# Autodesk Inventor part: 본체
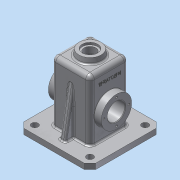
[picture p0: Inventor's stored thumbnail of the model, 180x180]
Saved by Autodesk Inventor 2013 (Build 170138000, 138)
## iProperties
Created: 2016-02
Part Number: 본체
Material: 알루미늄 6061
Document SubType Name: Modeling
Designer: dgall
Mass: 938.846 g
Surface Area: 1045.65 cm^2
Volume: 346.438 cm^3
Density: 2.71 g/cm^3
Author: dgall
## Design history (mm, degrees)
sketch "스케치1"
  geometry: L1 (-35, 35)-(35, 35); L2 (35, 35)-(35, -35); L3 (35, -35)-(-35, -35); L4 (-35, -35)-(-35, 35); 1 further point
  constraints: 8 end point, 2 parallel, 1 horizontal, 1 perpendicular
  dimensions: "d0" = 70 distance of L1.end L2.end; "d2" = 70 distance of L1.start L1.end; "d3" = 35 distance from line of point (0, 0) L1; "d4" = 35 distance from line of point (0, 0) L2
extrude "돌출1" new body sketch "스케치1" distance "d5" = 120; taper "d6" = 0 deg
feature "쉘1" dims "d7" = 5
fillet "모깎기1" dims "d8" = 8
fillet "모깎기2" dims "d9" = 8
fillet "모깎기3" dims "d10" = 3
fillet "모깎기4" dims "d11" = 3
sketch "스케치2"
  geometry: L1 (-35, 27)-(-35, -27) reference; L2 (-27, -35)-(27, -35) reference; L3 (35, -27)-(35, 27) reference; L4 (27, 35)-(-27, 35) reference; L5 (-65, 65)-(65, 65); L6 (65, 65)-(65, -65); L7 (65, -65)-(-65, -65); L8 (-65, -65)-(-65, 65); A1 r 8 centre (-27, 27) between (-27, 35) and (-35, 27) reference; A2 r 8 centre (-27, -27) between (-35, -27) and (-27, -35) reference; A3 r 8 centre (27, -27) between (27, -35) and (35, -27) reference; A4 r 8 centre (27, 27) between (35, 27) and (27, 35) reference; 1 further point
  constraints: 8 end point, 2 parallel, 1 horizontal, 1 perpendicular
  dimensions: "d12" = 130 distance of L5.start L5.end; "d14" = 130 distance of L5.end L6.end; "d15" = 65 distance from line of point (0, 0) L6; "d16" = 65 distance from line of point (0, 0) L5
extrude "돌출2" join sketch "스케치2" distance "d17" = 10; taper "d18" = 0 deg
sketch "스케치3"
  geometry: L1 (-35, 10)-(-35, 112) reference; L2 (65, 10)-(-65, 10) reference; L3 (-50, 10)-(-35, 95.069); L4 (-65, 0)-(-65, 10) reference; 1 further point
  constraints: 2 end point, 2 point on line
  dimensions: "d19" = 15 distance from line of L3.start L4; "d20" = 10 deg angle of L4 L3
feature "리브1" sketch "스케치3" dims "d21" = 1, "d22" = 10, "d23" = 0, "d24" = 0, "d25" = 1, "d26" = 1
sketch "스케치4"
  geometry: L1 (35, 10)-(27, 10) reference; L2 (27, 10)-(27, 112) reference; L3 (35, 112)-(27, 112) reference; L4 (35, 112)-(35, 10) reference; L5 (65, 10)-(-65, 10) reference; L6 (35, 95.069)-(50, 10); L7 (65, 0)-(65, 10) reference; 1 further point
  constraints: 2 end point, 2 point on line
  dimensions: "d27" = 15 distance from line of L7 L6.end; "d28" = 10 deg angle of L7 L6
feature "리브2" sketch "스케치4" dims "d29" = 1, "d30" = 10, "d31" = 0, "d32" = 0, "d33" = 1, "d34" = 1
node "작업 평면1"
sketch "스케치5"
  geometry: C1 r 27.5 at (0, 55); 1 further point
  constraints: 1 centre point
  dimensions: "d36" = 55 diameter of C1; "d38" = 55 distance of point (0, 0) C1.centre; "d39" = 0 horizontal distance of point (0, 0) C1.centre
extrude "돌출3" join sketch "스케치5" stored distance "d40" = 10; taper "d41" = 0 deg
node "작업 평면2"
sketch "스케치6"
  geometry: C1 r 27.5 at (0, 55); 1 further point
  constraints: 1 centre point
  dimensions: "d43" = 55 diameter of C1; "d45" = 55 distance of point (0, 0) C1.centre; "d46" = 0 horizontal distance of point (0, 0) C1.centre
extrude "돌출4" join sketch "스케치6" stored distance "d47" = 10; taper "d48" = 0 deg
sketch "스케치7"
  geometry: C1 r 27.5 at (0, 0) reference; C2 r 16 at (0, 0); 1 further point
  constraints: 1 centre point, 1 coincident
  dimensions: "d49" = 32 diameter of C2
extrude "돌출5" cut sketch "스케치7" stored distance "d51" = 10; taper "d52" = 0 deg
sketch "스케치8"
  geometry: L1 (30, 112)-(30, 0) reference; L2 (-30, 0)-(-30, 112) reference; L3 (-48, 27.5)-(-48, 82.5) reference; L4 (48, 82.5)-(48, 27.5) reference; L5 (78.131, 55)-(-93.042, 55); L6 (30, 82.5)-(23, 75.5); L7 (23, 75.5)-(23, 55); L8 (30, 82.5)-(30, 55); L9 (23, 55)-(30, 55); 1 further point
  constraints: 10 end point, 4 point on line, 2 perpendicular, 1 collinear
  dimensions: "d53" = 55 distance from line of point (0, 0) L5; "d54" = 7 distance between parallel lines of L7 L1; "d55" = 55 diameter of L6.start L5; "d56" = 135 deg angle of L6 L7
revolve "회전1" sketch "스케치8" stored, may be unused: angle "d57" = 90 deg
sketch "스케치9"
  geometry: C1 r 16 at (0, 0) reference; 1 further point
extrude "돌출6" cut sketch "스케치9" stored distance "d58" = 10; taper "d59" = 0 deg
sketch "스케치10"
  geometry: L1 (71.465, 55)-(-61.462, 55); L2 (-30, 0)-(-30, 112) reference; L3 (-23, 55)-(-23, 34.5); L4 (-23, 34.5)-(-30, 27.5); L5 (-30, 55)-(-30, 27.5); L6 (-30, 55)-(-23, 55); 1 further point
  constraints: 10 end point, 4 point on line, 2 collinear, 1 horizontal, 1 perpendicular
  dimensions: "d60" = 55 distance from line of L1 point (0, 0); "d62" = 135 deg angle of L3 L4; "d63" = 55 diameter of L4.end L1; "d64" = 7 distance between parallel lines of L2 L3
revolve "회전2" sketch "스케치10" stored, may be unused: angle "d65" = 90 deg
sketch "스케치11"
  geometry: C1 r 16 at (0, 0) reference; 1 further point
extrude "돌출7" cut sketch "스케치11" stored distance "d66" = 10; taper "d67" = 0 deg
node "작업 평면3"
sketch "스케치12"
  geometry: C1 r 20 at (0, 0); 1 further point
  constraints: 1 centre point, 1 coincident
  dimensions: "d69" = 40 diameter of C1
extrude "돌출8" join sketch "스케치12" stored distance "d71" = 10; taper "d72" = 10 deg
sketch "스케치13"
  geometry: C1 r 20 at (0, 0) reference; C2 r 14 at (0, 0)
  constraints: 1 centre point, 1 coincident
  dimensions: "d73" = 28 diameter of C2
extrude "돌출9" cut sketch "스케치13" distance "d75" = 4; taper "d76" = 0 deg
sketch "스케치14"
  geometry: C1 r 14 at (0, 0) reference; C2 r 10.5 at (0, 0)
  constraints: 1 centre point, 1 coincident
  dimensions: "d77" = 21 diameter of C2
extrude "돌출10" cut sketch "스케치14" stored distance "d79" = 4; taper "d80" = 0 deg
chamfer "모따기1" distance "d81" = 10; stored, may be unused: second distance "d82" = 2, angle "d83" = 45 deg
sketch "스케치15"
  geometry: L1 (-65, 55)-(-65, -55) reference; L2 (-55, -65)-(55, -65) reference; L3 (65, -55)-(65, 55) reference; L4 (55, 65)-(-55, 65) reference; C1 r 6 at (-50, 50); C2 r 6 at (50, 50); C3 r 6 at (50, -50); C4 r 6 at (-50, -50); 1 further point
  constraints: 4 centre point
  dimensions: "d84" = 15 distance from line of C2.centre L3; "d85" = 15 distance from line of C2.centre L4; "d86" = 15 distance from line of C1.centre L4; "d87" = 15 distance from line of L1 C1.centre; "d88" = 15 distance from line of C4.centre L1; "d89" = 15 distance from line of L2 C4.centre; "d90" = 15 distance from line of L2 C3.centre; "d91" = 15 distance from line of C3.centre L3; "d92" = 12 diameter of C1; "d93" = 12 diameter of C2; "d94" = 12 diameter of C3; "d95" = 12 diameter of C4
extrude "돌출11" cut sketch "스케치15" stored distance "d96" = 4; taper "d97" = 0 deg
sketch "스케치16" dims "d98" = 45
  geometry: L1 (0, 0)-(-22.5, 0); C1 r 16 at (0, 0) reference; C2 r 27.5 at (0, 0) reference; C3 r 2 at (-22.5, 0); C4 r 2 at (0, -22.5); C5 r 2 at (22.5, 0); C6 r 2 at (0, 22.5); 1 further point
  constraints: 4 centre point, 2 coincident, 2 end point, 1 horizontal, 1 horizontal alignment, 11 other
  dimensions: "d100" = 4 diameter of C3; "d103" = 360 deg dimension on C1.centre C3.centre (derived)
hole "구멍1" sketch "스케치16" at (0, -22.5), (-22.5, 0), (0, 22.5), (22.5, 0) diameter "d105" = 3.459; stored, may be unused: countersink angle "d109" = 90 deg, drill point angle "d111" = 118 deg; dims "d106" = 8, "d107" = 4, "d108" = 2, "d110" = 10
fillet "모깎기5" dims "d112" = 3
fillet "모깎기6" dims "d113" = 3
fillet "모깎기7" dims "d114" = 3
fillet "모깎기8" dims "d115" = 0.5
sketch "스케치17"
  geometry: L1 (9, 7)-(9, 47); L2 (9, 47)-(15, 47); L3 (15, 47)-(15, 7); L4 (15, 7)-(9, 7); L5 (12, 47)-(12, 7); L6 (9, 27)-(15, 27); L7 (-18, 7)-(-18, 47) reference; 1 further point
  constraints: 4 end point, 4 midpoint, 2 other
  dimensions: "d117" = 0 distance from line of point (112, 27) L6; "d118" = 30 distance between parallel lines of L5 L7; "d119" = 6 distance between parallel lines of L3 L1; "d120" = 40 distance of L2.end L3.end
extrude "돌출12" join sketch "스케치17" distance "d121" = 0.5; taper "d122" = 0 deg
chamfer "모따기2" distance "d123" = 1; stored, may be unused: second distance "d124" = 2, angle "d125" = 45 deg
fillet "모깎기10" dims "d126" = 0.5
node "솔리드1"
mirror "대칭1"
node "투영된 루프1"
node "작업 평면4"
other parameters: "d35" = -48, "d42" = 48
